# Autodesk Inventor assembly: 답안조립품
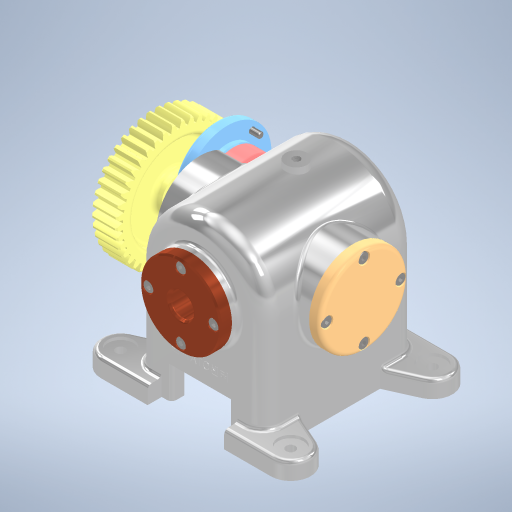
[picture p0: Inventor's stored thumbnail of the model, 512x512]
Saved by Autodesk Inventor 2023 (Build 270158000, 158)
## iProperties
Created: 2024-09
Part Number: 답안조립품
Document SubType Name: Assembly
Designer: home
Author: home
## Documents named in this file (11)
- C:\Users\home\Desktop\740904V1024\답안조립품.iam
- C:\Users\home\Desktop\740904V1024\본체.ipt
- C:\Users\home\Desktop\740904V1024\부시.ipt
- C:\Users\home\Desktop\740904V1024\육각 소켓 머리 볼트 M4x10.ipt
- C:\Users\home\Desktop\740904V1024\뒷커버.ipt
- C:\Users\home\Desktop\740904V1024\앞커버.ipt
- C:\Users\home\Desktop\740904V1024\깊은 홈 볼베어링 6203.ipt
- C:\Users\home\Desktop\740904V1024\편심축.ipt
- C:\Users\home\Desktop\740904V1024\평행키 3x3x14.ipt
- C:\Users\home\Desktop\740904V1024\오일실 17 32 8.ipt
- C:\Users\home\Desktop\740904V1024\스퍼 기어.ipt
